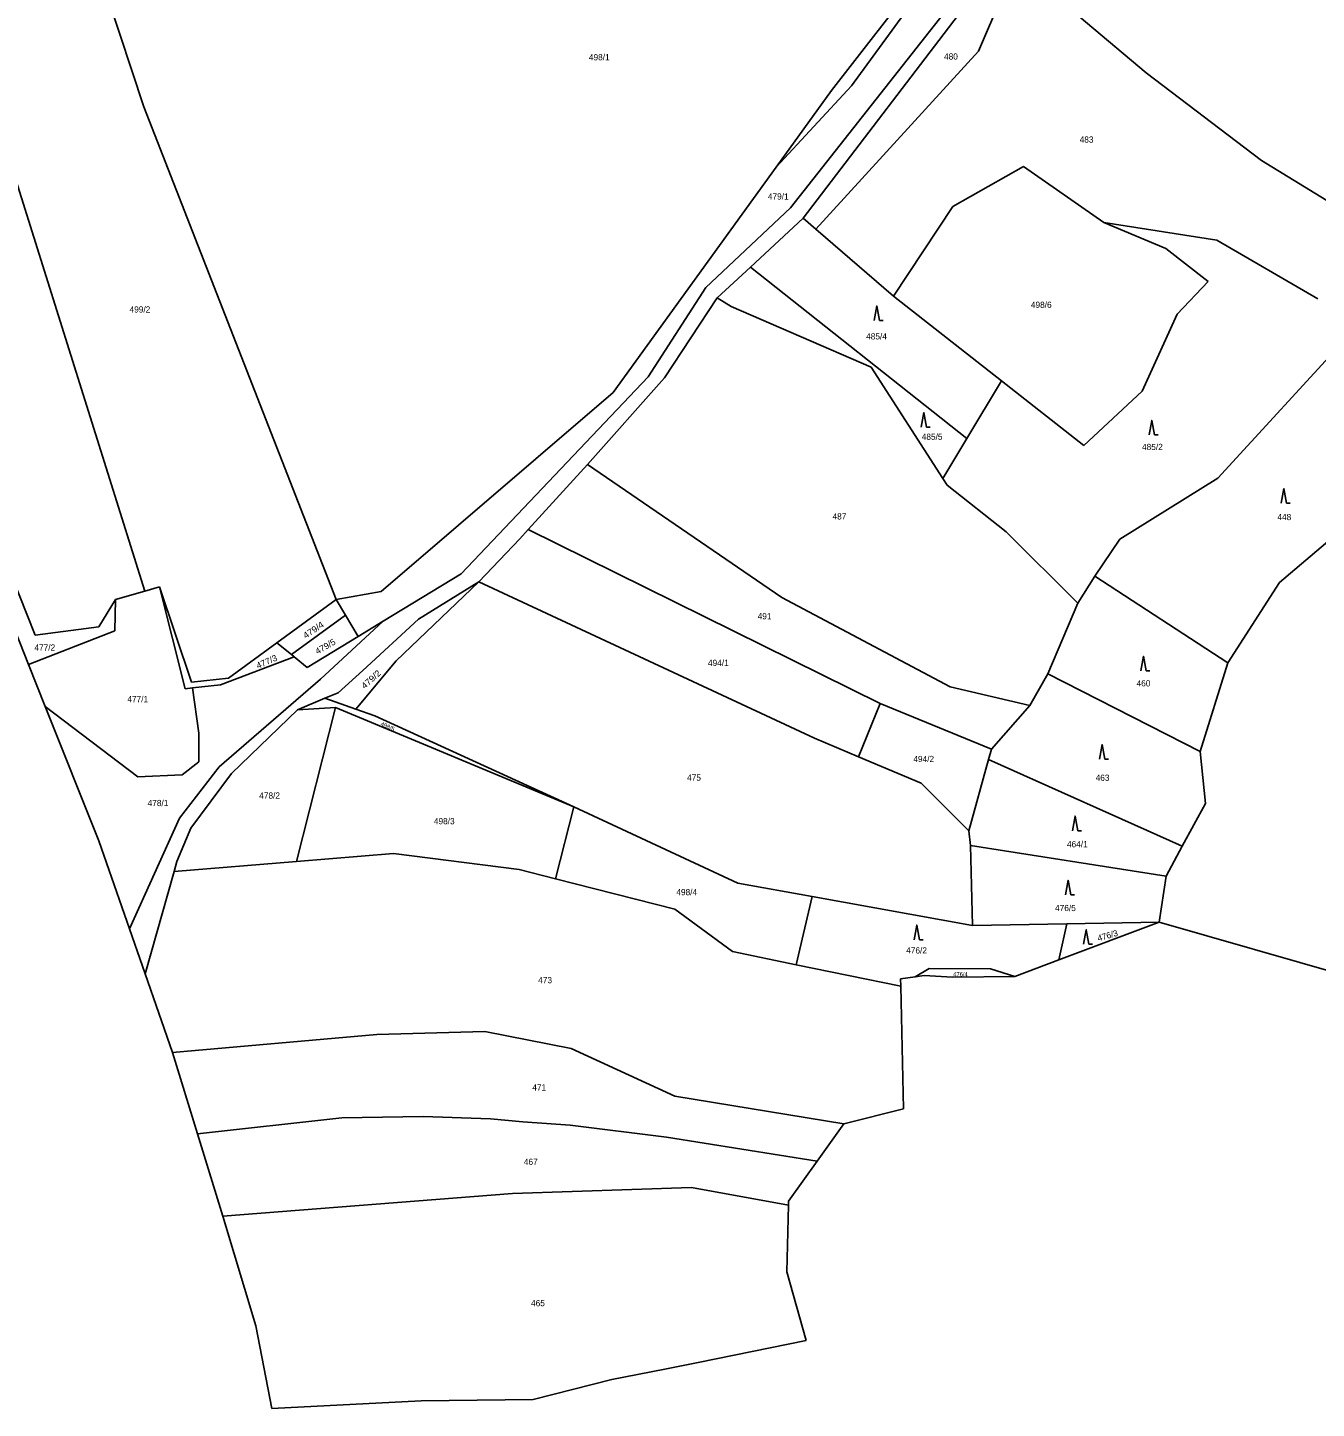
# Model space of a CAD drawing. Extents: x -664548 to -662415, y -1069720 to -1068208.
# Drawn here: x -664224.9 to -663871.7, y -1069720.1 to -1069341.5 of the extents above; entities that cross this region are included whole.
import ezdxf

# ---------------------------------------------------------------- set-up
doc = ezdxf.new("R2010")
doc.units = 0
doc.header["$LTSCALE"] = 0.68
doc.layers.add('1', color=7, linetype='Continuous', lineweight=25)
doc.layers.add('3', color=7, linetype='Continuous', lineweight=25)
doc.layers.add('2', color=7, linetype='Continuous')

msp = doc.modelspace()

# ---------------------------------------------------------------- linework, layer by layer
at = {"layer": '1'}
for p, q in [((-664012.33, -1069393.77), (-663928.47, -1069283.68)), ((-664247.65, -1069321.07), (-664192.8, -1069496)), ((-663953.93, -1069323.72), (-663964.29, -1069347.98)), ((-663953.93, -1069323.72), (-663918.34, -1069353.91)), ((-664203.39, -1069331.82), (-664193.07, -1069363.25)), ((-663969.18, -1069331.66), (-664015.79, -1069390.96)), ((-663978.86, -1069329.77), (-663999.13, -1069357.49)), ((-663964.29, -1069347.98), (-664008.84, -1069396.79)), ((-663918.34, -1069353.91), (-663886.73, -1069377.97)), ((-663999.13, -1069357.49), (-664019.73, -1069379.75)), ((-664193.07, -1069363.25), (-664140.29, -1069498.29)), ((-663886.73, -1069377.97), (-663854.69, -1069397.6)), ((-664064.37, -1069441.52), (-664019.73, -1069379.75)), ((-663971.36, -1069390.57), (-663951.96, -1069379.61)), ((-663951.96, -1069379.61), (-663929.92, -1069394.98)), ((-664015.79, -1069390.96), (-664039, -1069412.77)), ((-664026.78, -1069407.18), (-664012.33, -1069393.77)), ((-664012.33, -1069393.77), (-664008.84, -1069396.79)), ((-663987.61, -1069415.14), (-663971.36, -1069390.57)), ((-664008.84, -1069396.79), (-663987.61, -1069415.14)), ((-663929.92, -1069394.98), (-663912.92, -1069402.03)), ((-663929.92, -1069394.98), (-663899, -1069399.83)), ((-663871.25, -1069415.91), (-663899, -1069399.83)), ((-663912.92, -1069402.03), (-663901.3, -1069411.16)), ((-664035.91, -1069415.64), (-664026.78, -1069407.18)), ((-664026.78, -1069407.18), (-663967.49, -1069454.19)), ((-664039, -1069412.77), (-664054.79, -1069437.3)), ((-663909.86, -1069420.12), (-663901.3, -1069411.16)), ((-664035.91, -1069415.64), (-664050.32, -1069437.49)), ((-664035.91, -1069415.64), (-664032.09, -1069417.94)), ((-663987.61, -1069415.14), (-663958.02, -1069438.34)), ((-664032.09, -1069417.94), (-663993.74, -1069434.57)), ((-663919.43, -1069441.16), (-663909.86, -1069420.12)), ((-663898.67, -1069465.05), (-663861.66, -1069424.58)), ((-663993.74, -1069434.57), (-663974.04, -1069465.15)), ((-664054.79, -1069437.3), (-664106.05, -1069491.26)), ((-664050.32, -1069437.49), (-664071.48, -1069461.3)), ((-663967.49, -1069454.19), (-663958.02, -1069438.34)), ((-663958.02, -1069438.34), (-663935.4, -1069456.07)), ((-664128.02, -1069496.09), (-664064.37, -1069441.52)), ((-663935.4, -1069456.07), (-663919.43, -1069441.16)), ((-663974.04, -1069465.15), (-663967.49, -1069454.19)), ((-664071.48, -1069461.3), (-664087.67, -1069479.15)), ((-664018.21, -1069497.8), (-664071.48, -1069461.3)), ((-663974.04, -1069465.15), (-663972.86, -1069466.97)), ((-663898.67, -1069465.05), (-663925.58, -1069481.78)), ((-663972.86, -1069466.97), (-663956.67, -1069479.78)), ((-663881.76, -1069493.65), (-663856.36, -1069471.98)), ((-664087.67, -1069479.15), (-664089.99, -1069481.71)), ((-663991.25, -1069526.83), (-664087.67, -1069479.15)), ((-663956.67, -1069479.78), (-663937.05, -1069499.35)), ((-664089.99, -1069481.71), (-664101.2, -1069493.43)), ((-663925.58, -1069481.78), (-663932.38, -1069491.93)), ((-664229.34, -1069491.74), (-664222.8, -1069508.08)), ((-664106.05, -1069491.26), (-664127.47, -1069504.27)), ((-663932.38, -1069491.93), (-663937.05, -1069499.35)), ((-663895.94, -1069515.68), (-663932.38, -1069491.93)), ((-664233.83, -1069493), (-664224.61, -1069516.16)), ((-664200.77, -1069498.29), (-664192.8, -1069496)), ((-664192.8, -1069496), (-664188.75, -1069494.83)), ((-664188.75, -1069494.83), (-664179.97, -1069520.96)), ((-664188.75, -1069494.83), (-664181.7, -1069522.76)), ((-664101.2, -1069493.43), (-664123.87, -1069515.1)), ((-664101.2, -1069493.43), (-664117.79, -1069503.7)), ((-664101.2, -1069493.43), (-664009.21, -1069536.31)), ((-663895.94, -1069515.68), (-663881.76, -1069493.65)), ((-664205.38, -1069505.77), (-664200.77, -1069498.29)), ((-664200.77, -1069498.29), (-664200.99, -1069506.93)), ((-664156.58, -1069510.2), (-664140.29, -1069498.29)), ((-664140.29, -1069498.29), (-664128.02, -1069496.09)), ((-664140.29, -1069498.29), (-664137.76, -1069502.59)), ((-663972.03, -1069522.26), (-664018.21, -1069497.8)), ((-663937.05, -1069499.35), (-663945.31, -1069518.68)), ((-664152.6, -1069513.43), (-664137.76, -1069502.59)), ((-664137.76, -1069502.59), (-664134.33, -1069508.43)), ((-664200.99, -1069506.93), (-664224.61, -1069516.16)), ((-664222.8, -1069508.08), (-664205.38, -1069505.77)), ((-664144.58, -1069520.17), (-664127.47, -1069504.27)), ((-664127.47, -1069504.27), (-664134.33, -1069508.43)), ((-664117.79, -1069503.7), (-664133.05, -1069517.74)), ((-664169.83, -1069519.88), (-664156.58, -1069510.2)), ((-664152.6, -1069513.43), (-664156.58, -1069510.2)), ((-664134.33, -1069508.43), (-664148.3, -1069516.91)), ((-664172.06, -1069521.68), (-664151.82, -1069514.06)), ((-664151.82, -1069514.06), (-664152.6, -1069513.43)), ((-664148.3, -1069516.91), (-664151.82, -1069514.06)), ((-664224.61, -1069516.16), (-664220.05, -1069527.61)), ((-664133.05, -1069517.74), (-664139.82, -1069523.86)), ((-664123.87, -1069515.1), (-664134.94, -1069528.37)), ((-663945.31, -1069518.68), (-663950.21, -1069527.39)), ((-663903.54, -1069539.99), (-663945.31, -1069518.68)), ((-663903.54, -1069539.99), (-663895.94, -1069515.68)), ((-664181.7, -1069522.76), (-664179.74, -1069522.54)), ((-664179.97, -1069520.96), (-664169.83, -1069519.88)), ((-664179.74, -1069522.54), (-664172.06, -1069521.68)), ((-664179.74, -1069522.54), (-664177.95, -1069535)), ((-664172.43, -1069544.21), (-664144.58, -1069520.17)), ((-663950.21, -1069527.39), (-663972.03, -1069522.26)), ((-664143.44, -1069525.39), (-664150.9, -1069528.54)), ((-664139.82, -1069523.86), (-664143.44, -1069525.39)), ((-664134.94, -1069528.37), (-664143.44, -1069525.39)), ((-664220.05, -1069527.61), (-664205.35, -1069564.51)), ((-664194.7, -1069546.97), (-664220.05, -1069527.61)), ((-664169.02, -1069545.99), (-664150.9, -1069528.54)), ((-664140.47, -1069527.96), (-664151.24, -1069570.15)), ((-664150.9, -1069528.54), (-664140.47, -1069527.96)), ((-664140.47, -1069527.96), (-664075.19, -1069555.17)), ((-664129.74, -1069530.19), (-664134.94, -1069528.37)), ((-663997.14, -1069541.43), (-663991.25, -1069526.83)), ((-663991.25, -1069526.83), (-663960.71, -1069539.34)), ((-663950.21, -1069527.39), (-663960.71, -1069539.34)), ((-664075.19, -1069555.17), (-664129.74, -1069530.19)), ((-664177.95, -1069535), (-664177.95, -1069542.81)), ((-663997.14, -1069541.43), (-664009.21, -1069536.31)), ((-663980.04, -1069548.68), (-663997.14, -1069541.43)), ((-663960.71, -1069539.34), (-663961.5, -1069542.18)), ((-663902.03, -1069554.23), (-663903.54, -1069539.99)), ((-664183.28, -1069558.3), (-664172.43, -1069544.21)), ((-664177.95, -1069542.81), (-664182.49, -1069546.34)), ((-663961.5, -1069542.18), (-663966.9, -1069561.73)), ((-663961.5, -1069542.18), (-663908.43, -1069565.98)), ((-664182.49, -1069546.34), (-664194.7, -1069546.97)), ((-664180.17, -1069560.97), (-664169.02, -1069545.99)), ((-663980.04, -1069548.68), (-663966.9, -1069561.73)), ((-664075.19, -1069555.17), (-664080.21, -1069574.89)), ((-664075.19, -1069555.17), (-664030.23, -1069576.11)), ((-663908.43, -1069565.98), (-663902.03, -1069554.23)), ((-664197, -1069588.57), (-664183.28, -1069558.3)), ((-664183.99, -1069570.18), (-664180.17, -1069560.97)), ((-663966.9, -1069561.73), (-663966.47, -1069565.76)), ((-664205.35, -1069564.51), (-664197, -1069588.57)), ((-664124.58, -1069567.98), (-664151.24, -1069570.15)), ((-664090.18, -1069572.37), (-664124.58, -1069567.98)), ((-663966.47, -1069565.76), (-663912.86, -1069574.13)), ((-663966.47, -1069565.76), (-663965.89, -1069587.65)), ((-663912.86, -1069574.13), (-663908.43, -1069565.98)), ((-664151.24, -1069570.15), (-664184.75, -1069572.88)), ((-664183.99, -1069570.18), (-664184.75, -1069572.88)), ((-664184.75, -1069572.88), (-664192.7, -1069600.97)), ((-664080.21, -1069574.89), (-664090.18, -1069572.37)), ((-664047.5, -1069583.17), (-664080.21, -1069574.89)), ((-663912.86, -1069574.13), (-663914.77, -1069586.75)), ((-664030.23, -1069576.11), (-664009.85, -1069579.77)), ((-664009.85, -1069579.77), (-664014.26, -1069598.44)), ((-664009.85, -1069579.77), (-663965.89, -1069587.65)), ((-664031.74, -1069594.83), (-664047.5, -1069583.17)), ((-663942.29, -1069597.14), (-663914.77, -1069586.75)), ((-663940.1, -1069587.2), (-663914.77, -1069586.75)), ((-663862.74, -1069601.74), (-663914.77, -1069586.75)), ((-664197, -1069588.57), (-664192.7, -1069600.97)), ((-663965.89, -1069587.65), (-663940.1, -1069587.2)), ((-663940.1, -1069587.2), (-663942.29, -1069597.14)), ((-664014.26, -1069598.44), (-664031.74, -1069594.83)), ((-663954.29, -1069601.67), (-663942.29, -1069597.14)), ((-664192.7, -1069600.97), (-664185.22, -1069622.51)), ((-663985.58, -1069604.37), (-664014.26, -1069598.44)), ((-663985.63, -1069602.35), (-663981.62, -1069601.78)), ((-663981.62, -1069601.78), (-663977.78, -1069599.48)), ((-663981.62, -1069601.78), (-663979.21, -1069601.44)), ((-663979.21, -1069601.44), (-663971.41, -1069601.82)), ((-663977.78, -1069599.48), (-663961.01, -1069599.55)), ((-663971.41, -1069601.82), (-663954.29, -1069601.67)), ((-663961.01, -1069599.55), (-663954.29, -1069601.67)), ((-663985.58, -1069604.37), (-663985.63, -1069602.35)), ((-663984.8, -1069637.96), (-663985.58, -1069604.37)), ((-664099.56, -1069616.74), (-664129.16, -1069617.62)), ((-664075.88, -1069621.4), (-664099.56, -1069616.74)), ((-664129.16, -1069617.62), (-664185.22, -1069622.51)), ((-664185.22, -1069622.51), (-664178.36, -1069644.82)), ((-664047.54, -1069634.51), (-664075.88, -1069621.4)), ((-664047.54, -1069634.51), (-664001.19, -1069642.03)), ((-663984.8, -1069637.96), (-664001.19, -1069642.03)), ((-664138.79, -1069640.46), (-664178.36, -1069644.82)), ((-664116.49, -1069640.08), (-664138.79, -1069640.46)), ((-664098.02, -1069640.68), (-664116.49, -1069640.08)), ((-664089.2, -1069641.56), (-664098.02, -1069640.68)), ((-664076.2, -1069642.44), (-664089.2, -1069641.56)), ((-664049.75, -1069645.75), (-664076.2, -1069642.44)), ((-664008.53, -1069652.32), (-664001.19, -1069642.03)), ((-664178.36, -1069644.82), (-664171.42, -1069667.37)), ((-664049.75, -1069645.75), (-664008.53, -1069652.32)), ((-664016.34, -1069663.26), (-664008.53, -1069652.32)), ((-664092.03, -1069661.21), (-664171.42, -1069667.37)), ((-664042.92, -1069659.5), (-664092.03, -1069661.21)), ((-664042.92, -1069659.5), (-664016.37, -1069664.37)), ((-664016.78, -1069682.63), (-664016.37, -1069664.37)), ((-664016.37, -1069664.37), (-664016.34, -1069663.26)), ((-664162.39, -1069697.5), (-664171.42, -1069667.37)), ((-664016.78, -1069682.63), (-664011.5, -1069701.48)), ((-664157.97, -1069720.09), (-664162.39, -1069697.5)), ((-664041.1, -1069707.49), (-664011.5, -1069701.48)), ((-664041.1, -1069707.49), (-664050.26, -1069709.31)), ((-664050.26, -1069709.31), (-664064.77, -1069712.13)), ((-664064.77, -1069712.13), (-664086.35, -1069717.64)), ((-664116.99, -1069718.04), (-664157.97, -1069720.09)), ((-664086.35, -1069717.64), (-664116.99, -1069718.04))]:
    msp.add_line(p, q, dxfattribs=at)
msp.add_lwpolyline([(-664019.73, -1069379.75), (-664004.55, -1069358.75), (-663926.13, -1069257.72)], dxfattribs=at)
at = {"layer": '3'}
for p, q in [((-663991.4, -1069421.8), (-663990.404, -1069421.8)), ((-663978.51, -1069451.06), (-663977.514, -1069451.06)), ((-663916.04, -1069453.2), (-663915.044, -1069453.2)), ((-663879.84, -1069471.89), (-663878.844, -1069471.89)), ((-663918.33, -1069517.86), (-663917.334, -1069517.86)), ((-663929.66, -1069542.09), (-663928.664, -1069542.09)), ((-663937.06, -1069561.71), (-663936.064, -1069561.71)), ((-663938.98, -1069579.29), (-663937.984, -1069579.29)), ((-663980.44, -1069591.59), (-663979.444, -1069591.59)), ((-663934.02, -1069592.84), (-663933.024, -1069592.84))]:
    msp.add_line(p, q, dxfattribs=at)
for points in [[(-663991.4, -1069421.8), (-663992.15, -1069417.8), (-663992.9, -1069421.8)], [(-663978.51, -1069451.06), (-663979.26, -1069447.06), (-663980.01, -1069451.06)], [(-663916.04, -1069453.2), (-663916.79, -1069449.2), (-663917.54, -1069453.2)], [(-663879.84, -1069471.89), (-663880.59, -1069467.89), (-663881.34, -1069471.89)], [(-663918.33, -1069517.86), (-663919.08, -1069513.86), (-663919.83, -1069517.86)], [(-663929.66, -1069542.09), (-663930.41, -1069538.09), (-663931.16, -1069542.09)], [(-663937.06, -1069561.71), (-663937.81, -1069557.71), (-663938.56, -1069561.71)], [(-663938.98, -1069579.29), (-663939.73, -1069575.29), (-663940.48, -1069579.29)], [(-663980.44, -1069591.59), (-663981.19, -1069587.59), (-663981.94, -1069591.59)], [(-663934.02, -1069592.84), (-663934.77, -1069588.84), (-663935.52, -1069592.84)]]:
    msp.add_lwpolyline(points, dxfattribs=at)

# ---------------------------------------------------------------- texts
at = {"layer": '2'}
for s, height, p in [('498/1', 1.7, (-664071.06, -1069350.475)), ('480', 1.7, (-663973.73, -1069350.275)), ('483', 1.7, (-663936.56, -1069373.054)), ('479/1', 1.7, (-664022.01, -1069388.655)), ('498/6', 1.7, (-663949.93, -1069418.344)), ('499/2', 1.7, (-664196.95, -1069419.635)), ('485/4', 1.7, (-663995.08, -1069427.005)), ('485/5', 1.7, (-663979.84, -1069454.535)), ('485/2', 1.7, (-663919.47, -1069457.334)), ('487', 1.7, (-664004.29, -1069476.375)), ('448', 1.7, (-663882.37, -1069476.545)), ('491', 1.7, (-664024.81, -1069503.745)), ('477/2', 1.7, (-664223.03, -1069512.324)), ('494/1', 1.7, (-664038.43, -1069516.525)), ('460', 1.7, (-663920.96, -1069522.145)), ('477/1', 1.7, (-664197.55, -1069526.465)), ('494/2', 1.7, (-663982.14, -1069542.885)), ('475', 1.7, (-664044.15, -1069547.985)), ('463', 1.7, (-663932.18, -1069548.035)), ('478/2', 1.7, (-664161.41, -1069552.905)), ('478/1', 1.7, (-664192, -1069554.955)), ('498/3', 1.7, (-664113.55, -1069559.925)), ('464/1', 1.7, (-663940.04, -1069566.245)), ('498/4', 1.7, (-664047.09, -1069579.385)), ('476/5', 1.7, (-663943.3, -1069583.745)), ('476/2', 1.7, (-663984.11, -1069595.365)), ('473', 1.7, (-664084.96, -1069603.515)), ('476/4', 1.14, (-663971.19, -1069601.615)), ('471', 1.7, (-664086.58, -1069632.935)), ('467', 1.7, (-664088.89, -1069653.324)), ('465', 1.7, (-664086.92, -1069692.084))]:
    msp.add_text(s, height=height, dxfattribs=at).set_placement(p)
for s, height, rotation, width, p in [('479/4', 1.7, 34, 1.1, (-664148.682, -1069509.122)), ('479/5', 1.7, 30, 1.05, (-664145.457, -1069513.418)), ('477/3', 1.7, 24, 1.05, (-664161.757, -1069517.348)), ('479/2', 1.7, 42, 1.1, (-664132.535, -1069522.935)), ('498/5', 1.14, 336, 1.05, (-664128.265, -1069532.83))]:
    msp.add_text(s, height=height, rotation=rotation, dxfattribs=dict(at, width=width)).set_placement(p)
msp.add_text('476/3', height=1.7, rotation=16, dxfattribs=at).set_placement((-663931.412, -1069592.058))

doc.saveas('drawing.dxf')
